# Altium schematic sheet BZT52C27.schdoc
size 127 x 101 mm
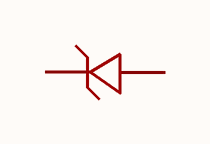
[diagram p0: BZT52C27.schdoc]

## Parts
D?  bzt52c27_c81935  [SOD-123_L2.7-W1.6-LS3.7-RD]  (value not drawn)

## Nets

Not connected (* = marked no-connect by the designer): D? 1(C) 2(A)

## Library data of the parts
D? = bzt52c27_c81935: 二极管配置:1个独立式;稳压值(标称值):27V;稳压值(范围):25.1V~28.9V;耗散功率(Pd):500mW;; Manufacturer: CJ(江苏长电/长晶); AddInBom: yes; ModelId: ad7e39f9e5534b3c96ffdc5532ebb493; ModelName: SOD-123_L2.7-W1.6-H1.4-LS3.7; ModelTransform: 146.026,62.992,0,180,0,0,0.0005,0,0; Diode Configuration: 1个独立式; Zener Voltage(Nom): 27V; Reverse Leakage Current (Ir): 100nA; Pd - Power Dissipation: 500mW; Impedance(Zzt): 80Ω; Impedance(Zzk): 300Ω; Operating Junction Temperature Range: -55℃~+150℃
